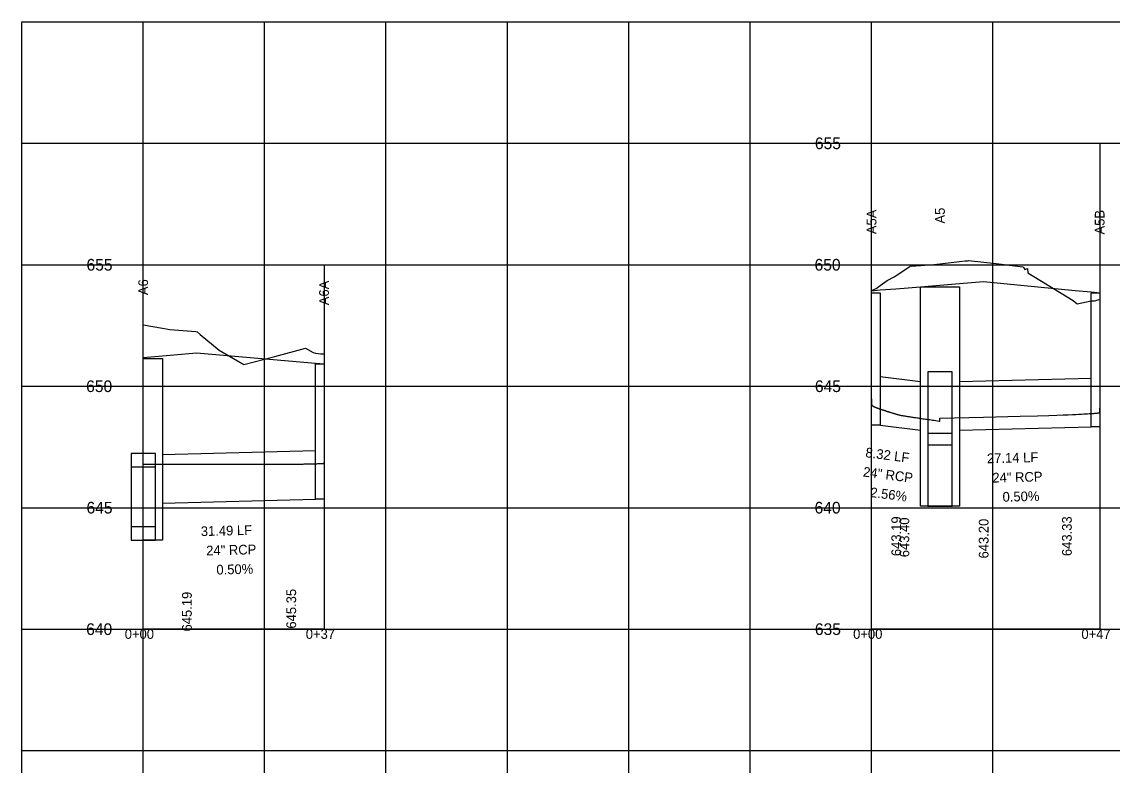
# Model space of a CAD drawing. Extents: x 2252703 to 2264864, y 13787568 to 13790989.
# Drawn here: x 2264413.7 to 2264638.2, y 13787715.1 to 13787868.1 of the extents above; entities that cross this region are included whole.
import ezdxf

# ---------------------------------------------------------------- set-up
doc = ezdxf.new("R2010")
doc.units = 0
for name, color, linetype in [('blank4', 7, 'Continuous'), ('BORD_grid_bottom_major_5int', 7, 'Continuous'), ('D_DRN_PROF_HGL', 7, 'Continuous'), ('D_PROF_1', 7, 'Continuous'), ('D_PROF_NOTES_1', 7, 'Continuous'), ('Default', 7, 'Continuous'), ('Drain_PipeInside', 7, 'Continuous'), ('E_Terrain', 7, 'Continuous'), ('Inlet', 7, 'Continuous'), ('z - Construction', 7, 'Continuous')]:
    doc.layers.add(name, color=color, linetype=linetype)

msp = doc.modelspace()

# ---------------------------------------------------------------- linework, layer by layer
at = {"layer": 'blank4'}
for points in [[(2264588.67, 13787743.09), (2264588.67, 13787843.09), (2264635.64, 13787843.09), (2264635.64, 13787743.09)], [(2264438.67, 13787743.09), (2264438.67, 13787818.09), (2264475.91, 13787818.09), (2264475.91, 13787743.09)]]:
    msp.add_lwpolyline(points, close=True, dxfattribs=at)
at = {"layer": 'BORD_grid_bottom_major_5int'}
for p, q in [((2264413.67, 13787868.09), (2264838.67, 13787868.09)), ((2264413.67, 13787568.09), (2264413.67, 13787868.09)), ((2264438.67, 13787568.09), (2264438.67, 13787868.09)), ((2264463.67, 13787568.09), (2264463.67, 13787868.09)), ((2264488.67, 13787568.09), (2264488.67, 13787868.09)), ((2264513.67, 13787568.09), (2264513.67, 13787868.09)), ((2264538.67, 13787568.09), (2264538.67, 13787868.09)), ((2264563.67, 13787568.09), (2264563.67, 13787868.09)), ((2264588.67, 13787568.09), (2264588.67, 13787868.09)), ((2264613.67, 13787568.09), (2264613.67, 13787868.09)), ((2264413.67, 13787843.09), (2264838.67, 13787843.09)), ((2264413.67, 13787818.09), (2264838.67, 13787818.09)), ((2264413.67, 13787793.09), (2264838.67, 13787793.09)), ((2264413.67, 13787768.09), (2264838.67, 13787768.09)), ((2264413.67, 13787743.09), (2264838.67, 13787743.09)), ((2264413.67, 13787718.09), (2264738.67, 13787718.09))]:
    msp.add_line(p, q, dxfattribs=at)
at = {"layer": 'D_DRN_PROF_HGL'}
msp.add_line((2264602.75, 13787785.9), (2264602.75, 13787786.51), dxfattribs=at)
for points in [[(2264588.67, 13787790.51), (2264588.67, 13787789.27), (2264588.67, 13787789.27), (2264588.67, 13787789.26), (2264588.67, 13787789.26), (2264588.67, 13787789.25), (2264588.68, 13787789.25), (2264588.68, 13787789.24), (2264588.68, 13787789.24), (2264588.68, 13787789.23), (2264588.69, 13787789.23), (2264588.69, 13787789.22), (2264588.69, 13787789.21), (2264588.7, 13787789.21), (2264588.7, 13787789.2), (2264588.71, 13787789.2), (2264588.71, 13787789.19), (2264588.72, 13787789.18), (2264588.72, 13787789.18), (2264588.73, 13787789.17), (2264588.74, 13787789.16), (2264588.74, 13787789.16), (2264588.75, 13787789.15), (2264588.76, 13787789.14), (2264588.77, 13787789.14), (2264588.78, 13787789.13), (2264588.79, 13787789.12), (2264588.8, 13787789.11), (2264588.81, 13787789.11), (2264588.82, 13787789.1), (2264588.83, 13787789.09), (2264588.84, 13787789.08), (2264588.85, 13787789.07), (2264588.86, 13787789.07), (2264588.88, 13787789.06), (2264588.89, 13787789.05), (2264588.91, 13787789.04), (2264588.92, 13787789.03), (2264588.94, 13787789.02), (2264588.95, 13787789.01), (2264588.97, 13787789), (2264588.98, 13787788.99), (2264589, 13787788.99), (2264589.02, 13787788.98), (2264589.04, 13787788.97), (2264589.06, 13787788.96), (2264589.08, 13787788.95), (2264589.1, 13787788.94), (2264589.12, 13787788.93), (2264589.14, 13787788.92), (2264589.16, 13787788.9), (2264589.18, 13787788.89), (2264589.21, 13787788.88), (2264589.23, 13787788.87), (2264589.25, 13787788.86), (2264589.28, 13787788.85), (2264589.31, 13787788.84), (2264589.33, 13787788.83), (2264589.36, 13787788.81), (2264589.39, 13787788.8), (2264589.42, 13787788.79), (2264589.45, 13787788.78), (2264589.48, 13787788.76), (2264589.51, 13787788.75), (2264589.54, 13787788.74), (2264589.57, 13787788.72), (2264589.6, 13787788.71), (2264589.64, 13787788.7), (2264589.67, 13787788.68), (2264589.71, 13787788.67), (2264589.74, 13787788.66), (2264589.78, 13787788.64), (2264589.82, 13787788.63), (2264589.86, 13787788.61), (2264589.9, 13787788.6), (2264589.94, 13787788.58), (2264589.98, 13787788.56), (2264590.02, 13787788.55), (2264590.07, 13787788.53), (2264590.11, 13787788.52), (2264590.16, 13787788.5), (2264590.2, 13787788.48), (2264590.25, 13787788.47), (2264590.3, 13787788.45), (2264590.35, 13787788.43), (2264590.4, 13787788.41), (2264590.45, 13787788.39), (2264590.5, 13787788.38), (2264590.56, 13787788.36), (2264590.61, 13787788.34), (2264590.67, 13787788.32), (2264590.73, 13787788.3), (2264590.79, 13787788.28), (2264590.85, 13787788.26), (2264590.91, 13787788.24), (2264590.97, 13787788.22), (2264591.03, 13787788.2), (2264591.1, 13787788.17), (2264591.16, 13787788.15), (2264591.23, 13787788.13), (2264591.3, 13787788.11), (2264591.37, 13787788.08), (2264591.44, 13787788.06), (2264591.52, 13787788.04), (2264591.59, 13787788.01), (2264591.67, 13787787.99), (2264591.75, 13787787.96), (2264591.83, 13787787.94), (2264591.91, 13787787.91), (2264592, 13787787.88), (2264592.08, 13787787.86), (2264592.17, 13787787.83), (2264592.26, 13787787.8), (2264592.35, 13787787.77), (2264592.44, 13787787.75), (2264592.53, 13787787.72), (2264592.63, 13787787.69), (2264592.73, 13787787.66), (2264592.83, 13787787.63), (2264592.93, 13787787.59), (2264593.04, 13787787.56), (2264593.15, 13787787.53), (2264593.26, 13787787.5), (2264593.37, 13787787.46), (2264593.48, 13787787.43), (2264593.6, 13787787.39), (2264593.72, 13787787.36), (2264593.84, 13787787.32), (2264593.97, 13787787.28), (2264594.1, 13787787.25), (2264594.23, 13787787.21), (2264594.36, 13787787.17), (2264594.5, 13787787.14), (2264594.64, 13787787.12), (2264594.78, 13787787.09), (2264594.93, 13787787.07), (2264595.08, 13787787.04), (2264595.23, 13787787.02), (2264595.39, 13787787), (2264595.55, 13787786.97), (2264595.71, 13787786.94), (2264595.88, 13787786.92), (2264596.05, 13787786.89), (2264596.23, 13787786.86), (2264596.41, 13787786.83), (2264596.59, 13787786.81), (2264596.78, 13787786.78), (2264596.98, 13787786.75), (2264597.18, 13787786.72), (2264597.38, 13787786.68), (2264597.59, 13787786.65), (2264597.81, 13787786.62), (2264598.03, 13787786.59), (2264598.26, 13787786.55), (2264598.49, 13787786.52), (2264598.73, 13787786.48), (2264598.98, 13787786.45), (2264599.23, 13787786.41), (2264599.49, 13787786.37), (2264599.76, 13787786.33), (2264600.04, 13787786.29), (2264600.33, 13787786.25), (2264600.62, 13787786.21), (2264600.92, 13787786.16), (2264601.23, 13787786.12), (2264601.56, 13787786.07), (2264601.89, 13787786.02), (2264602.23, 13787785.97), (2264602.59, 13787785.92), (2264602.75, 13787785.9)], [(2264602.75, 13787786.51), (2264611.73, 13787786.74), (2264619.26, 13787786.94), (2264622.85, 13787787.03), (2264625.16, 13787787.09), (2264626.84, 13787787.14), (2264628.13, 13787787.18), (2264629.17, 13787787.21), (2264630.03, 13787787.24), (2264630.75, 13787787.28), (2264631.37, 13787787.32), (2264631.91, 13787787.35), (2264632.38, 13787787.38), (2264632.79, 13787787.4), (2264633.15, 13787787.42), (2264633.47, 13787787.45), (2264633.75, 13787787.46), (2264634, 13787787.48), (2264634.23, 13787787.5), (2264634.43, 13787787.51), (2264634.61, 13787787.53), (2264634.77, 13787787.54), (2264634.91, 13787787.55), (2264635.03, 13787787.56), (2264635.14, 13787787.57), (2264635.24, 13787787.58), (2264635.32, 13787787.59), (2264635.39, 13787787.6), (2264635.45, 13787787.61), (2264635.5, 13787787.62), (2264635.55, 13787787.62), (2264635.58, 13787787.63), (2264635.61, 13787787.64), (2264635.62, 13787787.64), (2264635.63, 13787787.65), (2264635.64, 13787787.65), (2264635.64, 13787788.6)], [(2264438.67, 13787777.04), (2264438.87, 13787777.04), (2264439.07, 13787777.04), (2264439.27, 13787777.04), (2264439.48, 13787777.04), (2264439.68, 13787777.04), (2264439.88, 13787777.04), (2264440.08, 13787777.04), (2264440.28, 13787777.04), (2264440.48, 13787777.04), (2264440.68, 13787777.04), (2264440.88, 13787777.04), (2264441.08, 13787777.04), (2264441.29, 13787777.04), (2264441.49, 13787777.04), (2264441.69, 13787777.04), (2264441.89, 13787777.04), (2264442.09, 13787777.04), (2264442.29, 13787777.04), (2264442.49, 13787777.04), (2264442.69, 13787777.04), (2264442.89, 13787777.04), (2264443.09, 13787777.04), (2264443.3, 13787777.04), (2264443.5, 13787777.04), (2264443.7, 13787777.04), (2264443.9, 13787777.04), (2264444.1, 13787777.04), (2264444.3, 13787777.04), (2264444.5, 13787777.04), (2264444.7, 13787777.04), (2264444.9, 13787777.04), (2264445.1, 13787777.04), (2264445.31, 13787777.04), (2264445.51, 13787777.04), (2264445.71, 13787777.04), (2264445.91, 13787777.04), (2264446.11, 13787777.04), (2264446.31, 13787777.04), (2264446.51, 13787777.04), (2264446.71, 13787777.04), (2264446.91, 13787777.04), (2264447.11, 13787777.04), (2264447.31, 13787777.04), (2264447.52, 13787777.04), (2264447.72, 13787777.04), (2264447.92, 13787777.04), (2264448.12, 13787777.04), (2264448.32, 13787777.04), (2264448.52, 13787777.04), (2264448.72, 13787777.04), (2264448.92, 13787777.04), (2264449.12, 13787777.04), (2264449.32, 13787777.04), (2264449.53, 13787777.04), (2264449.73, 13787777.04), (2264449.93, 13787777.04), (2264450.13, 13787777.04), (2264450.33, 13787777.04), (2264450.53, 13787777.04), (2264450.73, 13787777.04), (2264450.93, 13787777.04), (2264451.13, 13787777.04), (2264451.33, 13787777.04), (2264451.53, 13787777.04), (2264451.74, 13787777.04), (2264451.94, 13787777.04), (2264452.14, 13787777.04), (2264452.34, 13787777.04), (2264452.54, 13787777.04), (2264452.74, 13787777.04), (2264452.94, 13787777.04), (2264453.14, 13787777.04), (2264453.34, 13787777.04), (2264453.54, 13787777.04), (2264453.74, 13787777.04), (2264453.94, 13787777.04), (2264454.15, 13787777.04), (2264454.35, 13787777.04), (2264454.55, 13787777.04), (2264454.75, 13787777.04), (2264454.95, 13787777.04), (2264455.15, 13787777.04), (2264455.35, 13787777.04), (2264455.55, 13787777.04), (2264455.75, 13787777.04), (2264455.95, 13787777.04), (2264456.15, 13787777.05), (2264456.35, 13787777.05), (2264456.56, 13787777.05), (2264456.76, 13787777.05), (2264456.96, 13787777.05), (2264457.16, 13787777.05), (2264457.36, 13787777.05), (2264457.56, 13787777.05), (2264457.76, 13787777.05), (2264457.96, 13787777.05), (2264458.16, 13787777.05), (2264458.36, 13787777.05), (2264458.56, 13787777.05), (2264458.76, 13787777.05), (2264458.96, 13787777.05), (2264459.17, 13787777.05), (2264459.37, 13787777.05), (2264459.57, 13787777.05), (2264459.77, 13787777.05), (2264459.97, 13787777.05), (2264460.17, 13787777.05), (2264460.37, 13787777.05), (2264460.57, 13787777.05), (2264460.77, 13787777.05), (2264460.97, 13787777.05), (2264461.17, 13787777.05), (2264461.37, 13787777.05), (2264461.57, 13787777.05), (2264461.77, 13787777.05), (2264461.98, 13787777.05), (2264462.18, 13787777.05), (2264462.38, 13787777.05), (2264462.58, 13787777.05), (2264462.78, 13787777.05), (2264462.98, 13787777.05), (2264463.18, 13787777.05), (2264463.38, 13787777.05), (2264463.58, 13787777.05), (2264463.78, 13787777.05), (2264463.98, 13787777.05), (2264464.18, 13787777.05), (2264464.38, 13787777.05), (2264464.58, 13787777.05), (2264464.79, 13787777.05), (2264464.99, 13787777.05), (2264465.19, 13787777.05), (2264465.39, 13787777.05), (2264465.59, 13787777.05), (2264465.79, 13787777.05), (2264465.99, 13787777.05), (2264466.19, 13787777.05), (2264466.39, 13787777.05), (2264466.59, 13787777.05), (2264466.79, 13787777.05), (2264466.99, 13787777.05), (2264467.19, 13787777.05), (2264467.39, 13787777.05), (2264467.59, 13787777.05), (2264467.79, 13787777.05), (2264468, 13787777.05), (2264468.2, 13787777.05), (2264468.4, 13787777.05), (2264468.6, 13787777.05), (2264468.8, 13787777.05), (2264469, 13787777.05), (2264469.2, 13787777.05), (2264469.4, 13787777.05), (2264469.6, 13787777.05), (2264469.8, 13787777.05), (2264470, 13787777.05), (2264470.2, 13787777.05), (2264470.4, 13787777.05), (2264470.6, 13787777.06), (2264470.8, 13787777.06), (2264471, 13787777.07), (2264471.2, 13787777.07), (2264471.41, 13787777.08), (2264471.61, 13787777.08), (2264471.81, 13787777.09), (2264472.01, 13787777.09), (2264472.21, 13787777.1), (2264472.41, 13787777.1), (2264472.61, 13787777.11), (2264472.81, 13787777.11), (2264473.01, 13787777.12), (2264473.21, 13787777.12), (2264473.41, 13787777.13), (2264473.61, 13787777.13), (2264473.81, 13787777.14), (2264474.01, 13787777.14), (2264474.21, 13787777.15), (2264474.41, 13787777.15), (2264474.61, 13787777.16), (2264474.81, 13787777.16), (2264475.01, 13787777.17), (2264475.22, 13787777.17), (2264475.42, 13787777.18), (2264475.62, 13787777.18), (2264475.82, 13787777.19), (2264475.91, 13787777.19), (2264475.91, 13787777.41)]]:
    msp.add_lwpolyline(points, dxfattribs=at)
at = {"layer": 'D_PROF_1'}
for points in [[(2264588.67, 13787812.75), (2264590.42, 13787812.9), (2264590.42, 13787812.9), (2264593.63, 13787813.16), (2264598.75, 13787813.58), (2264598.75, 13787813.58), (2264602.75, 13787813.91), (2264602.75, 13787813.91), (2264606.75, 13787814.24), (2264606.75, 13787814.24), (2264611.75, 13787814.65), (2264630.57, 13787812.77), (2264633.89, 13787812.49), (2264633.89, 13787812.49), (2264635.64, 13787812.34)], [(2264438.67, 13787798.98), (2264442.67, 13787799.33), (2264442.67, 13787799.33), (2264449.67, 13787799.93), (2264474.16, 13787797.87), (2264474.16, 13787797.87), (2264475.91, 13787797.72), (2264475.91, 13787797.72)]]:
    msp.add_lwpolyline(points, dxfattribs=at)
at = {"layer": 'Drain_PipeInside'}
for p, q in [((2264590.42, 13787795.1), (2264598.75, 13787794.03)), ((2264606.75, 13787794.08), (2264633.89, 13787794.76)), ((2264590.42, 13787785.1), (2264598.75, 13787784.03)), ((2264606.75, 13787784.08), (2264633.89, 13787784.76)), ((2264442.67, 13787779.04), (2264474.16, 13787779.83)), ((2264442.67, 13787769.04), (2264474.16, 13787769.83))]:
    msp.add_line(p, q, dxfattribs=at)
for points in [[(2264600.25, 13787781.05), (2264605.25, 13787781.05), (2264605.25, 13787796.05), (2264600.25, 13787796.05)], [(2264600.25, 13787768.39), (2264605.25, 13787768.39), (2264605.25, 13787783.39), (2264600.25, 13787783.39)], [(2264436.17, 13787764.22), (2264441.17, 13787764.22), (2264441.17, 13787779.22), (2264436.17, 13787779.22)], [(2264436.17, 13787761.42), (2264441.17, 13787761.42), (2264441.17, 13787776.42), (2264436.17, 13787776.42)]]:
    msp.add_lwpolyline(points, close=True, dxfattribs=at)
at = {"layer": 'E_Terrain'}
for points in [[(2264588.67, 13787812.77), (2264589.61, 13787813.2), (2264590.42, 13787813.8), (2264590.42, 13787813.8), (2264591.85, 13787814.86), (2264593.35, 13787815.58), (2264596.56, 13787817.76), (2264596.8, 13787818.04), (2264596.84, 13787817.79), (2264598.75, 13787817.94), (2264598.75, 13787817.94), (2264601.51, 13787818.15), (2264602.75, 13787818.3), (2264602.75, 13787818.3), (2264606.75, 13787818.79), (2264606.75, 13787818.79), (2264607.93, 13787818.93), (2264608.16, 13787818.88), (2264608.44, 13787818.93), (2264608.65, 13787818.95), (2264614.32, 13787818.37), (2264619.85, 13787817.67), (2264620.03, 13787817.47), (2264620.24, 13787817.13), (2264620.79, 13787817.31), (2264620.88, 13787816.44), (2264630.2, 13787810.74), (2264630.99, 13787810.07), (2264633.89, 13787810.67), (2264633.89, 13787810.67), (2264633.94, 13787810.68), (2264634.56, 13787810.69), (2264635.31, 13787810.9), (2264635.64, 13787811.02)], [(2264438.67, 13787805.72), (2264442.67, 13787805.02), (2264442.67, 13787805.02), (2264444.13, 13787804.77), (2264449.52, 13787804.37), (2264449.8, 13787804.26), (2264450.42, 13787803.77), (2264454.33, 13787800.49), (2264459.41, 13787797.56), (2264465.77, 13787799.22), (2264472.1, 13787800.89), (2264473.67, 13787800), (2264474.16, 13787799.91), (2264474.16, 13787799.91), (2264475.22, 13787799.73), (2264475.91, 13787799.74)]]:
    msp.add_lwpolyline(points, dxfattribs=at)
at = {"layer": 'Inlet'}
for points in [[(2264588.67, 13787812.34), (2264590.42, 13787812.34), (2264590.42, 13787785.1), (2264588.67, 13787785.1)], [(2264598.75, 13787813.55), (2264606.75, 13787813.55), (2264606.75, 13787768.39), (2264598.75, 13787768.39)], [(2264633.89, 13787812.34), (2264635.64, 13787812.34), (2264635.64, 13787784.76), (2264633.89, 13787784.76)], [(2264438.67, 13787798.83), (2264442.67, 13787798.83), (2264442.67, 13787761.42), (2264438.67, 13787761.42)], [(2264474.16, 13787797.72), (2264475.91, 13787797.72), (2264475.91, 13787769.83), (2264474.16, 13787769.83)]]:
    msp.add_lwpolyline(points, close=True, dxfattribs=at)
at = {"layer": 'z - Construction'}
for p, q in [((2264588.67, 13787818.09), (2264635.64, 13787818.09)), ((2264438.67, 13787793.09), (2264475.91, 13787793.09)), ((2264588.67, 13787793.09), (2264635.64, 13787793.09)), ((2264438.67, 13787768.09), (2264475.91, 13787768.09)), ((2264588.67, 13787768.09), (2264635.64, 13787768.09))]:
    msp.add_line(p, q, dxfattribs=at)

# ---------------------------------------------------------------- texts
at = {"layer": 'D_PROF_NOTES_1'}
for s, rotation, p in [('A5', 90, (2264603.75, 13787826.57)), ('A5A', 90, (2264589.67, 13787824.38)), ('A5B', 90, (2264636.64, 13787824.32)), ('A6', 90, (2264439.67, 13787811.84)), ('A6A', 90, (2264476.91, 13787809.76)), ('8.32 LF', 352.7097, (2264587.32, 13787778.5)), ('27.14 LF', 1.4321, (2264612.46, 13787777.23)), ('24" RCP', 352.7097, (2264586.82, 13787774.53)), ('24" RCP', 1.4321, (2264613.57, 13787773.25)), ('2.56%', 352.7097, (2264588.31, 13787770.31)), ('0.50%', 1.4321, (2264615.67, 13787769.31)), ('31.49 LF', 1.4321, (2264450.56, 13787762.24)), ('643.19', 90, (2264594.75, 13787758.12)), ('643.40', 90, (2264596.42, 13787757.89)), ('643.20', 90, (2264612.75, 13787757.64)), ('643.33', 90, (2264629.89, 13787758.13)), ('24" RCP', 1.4321, (2264451.67, 13787758.26)), ('0.50%', 1.4321, (2264453.77, 13787754.32)), ('645.35', 90, (2264470.16, 13787743.2)), ('645.19', 90, (2264448.67, 13787742.61))]:
    msp.add_text(s, height=2, rotation=rotation, dxfattribs=at).set_placement(p)
at = {"layer": 'Default'}
for s, height, p in [('655', 2.4, (2264577, 13787841.89)), ('655', 2.4, (2264427, 13787816.89)), ('650', 2.4, (2264576.93, 13787816.89)), ('650', 2.4, (2264426.93, 13787791.89)), ('645', 2.4, (2264577, 13787791.89)), ('645', 2.4, (2264427, 13787766.89)), ('640', 2.4, (2264576.93, 13787766.89)), ('640', 2.4, (2264426.93, 13787741.89)), ('635', 2.4, (2264577, 13787741.89)), ('0+00', 2, (2264434.87, 13787741.09)), ('0+37', 2, (2264472.15, 13787741.09)), ('0+00', 2, (2264584.87, 13787741.09)), ('0+47', 2, (2264631.88, 13787741.09))]:
    msp.add_text(s, height=height, dxfattribs=at).set_placement(p)

doc.saveas('drawing.dxf')
